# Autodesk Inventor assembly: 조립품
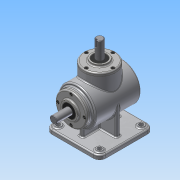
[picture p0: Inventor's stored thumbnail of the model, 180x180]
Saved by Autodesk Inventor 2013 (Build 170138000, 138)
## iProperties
Created: 2015-07
Part Number: 조립품
Document SubType Name: Assembly
Designer: ST
Author: ST
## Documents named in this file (14)
- C:\Users\ST\Desktop\450705V1009\조립품.iam
- C:\Users\ST\Desktop\450705V1009\본체.ipt
- C:\Users\ST\Desktop\450705V1009\M4.ipt
- C:\Users\ST\Desktop\450705V1009\메인 베벨기어.ipt
- C:\Users\ST\Desktop\450705V1009\메인 축.ipt
- 메인 축.ipt
- C:\Users\ST\Desktop\450705V1009\베어링 6203.ipt
- C:\Users\ST\Desktop\450705V1009\서브 베벨기어.ipt
- C:\Users\ST\Desktop\450705V1009\서브 축.ipt
- 서브 축.ipt
- C:\Users\ST\Desktop\450705V1009\오일실.ipt
- C:\Users\ST\Desktop\450705V1009\커버.ipt
- C:\Users\ST\Desktop\450705V1009\키 4x4.ipt
- C:\Users\ST\Desktop\450705V1009\키 5x5.ipt
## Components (8 placed, 1 different names)
1. M4:1
2. M4:2
3. M4:3
4. M4:4
5. M4:5
6. M4:6
7. M4:7
8. M4:8
